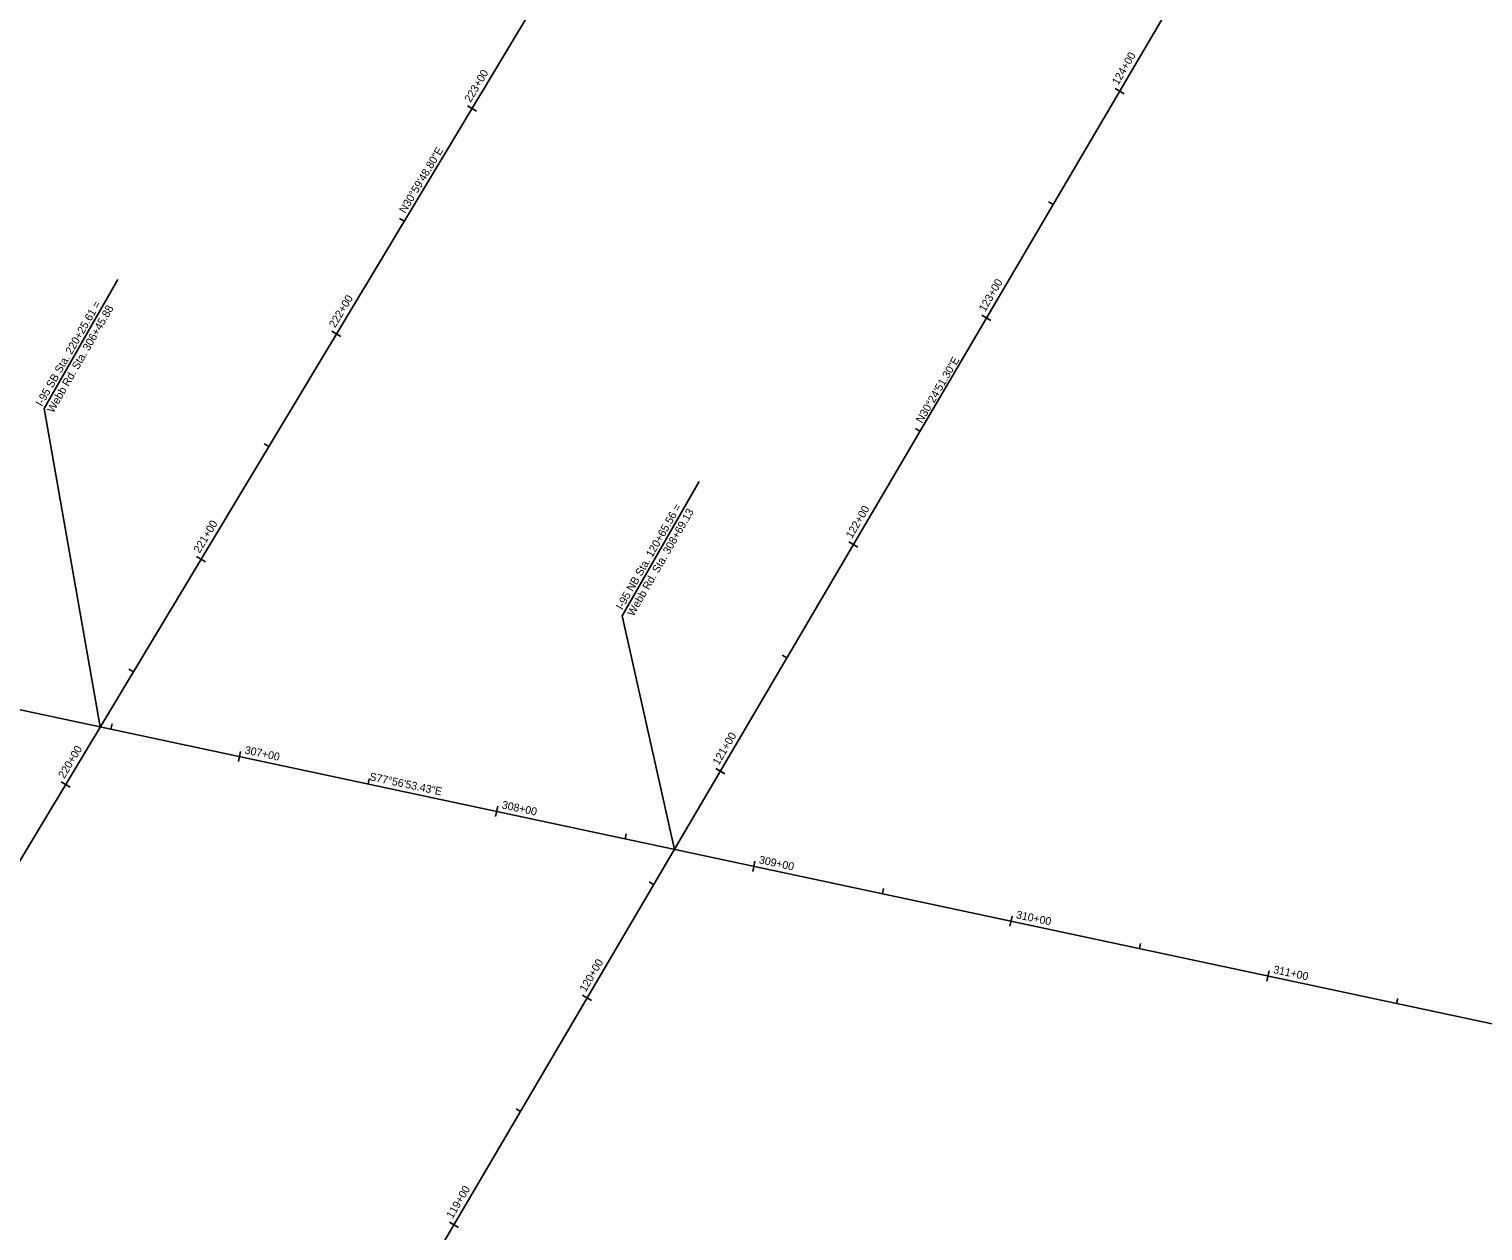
# Model space of a CAD drawing. Extents: x 1160279 to 1162288, y 615379 to 618896.
# Drawn here: x 1161178 to 1161731, y 617118 to 617576 of the extents above; entities that cross this region are included whole.
import ezdxf

# ---------------------------------------------------------------- set-up
doc = ezdxf.new("R2010")
doc.units = 0
for name, color, linetype in [('BRIDGE_TITLE', 7, 'Continuous'), ('FRAME', 7, 'Continuous'), ('HIGHWAY_TITLE', 7, 'Continuous'), ('MEDIUM', 7, 'Continuous')]:
    doc.layers.add(name, color=color, linetype=linetype)

msp = doc.modelspace()

# ---------------------------------------------------------------- linework, layer by layer
at = {"layer": 'FRAME'}
for p, q in [((1161056.19, 617062.15), (1162120.52, 618833.71)), ((1161209.81, 616899.51), (1162286.6, 618733.81)), ((1160573.57, 617445.06), (1162040.51, 617131.87))]:
    msp.add_line(p, q, dxfattribs=at)
at = {"layer": 'HIGHWAY_TITLE'}
for points in [[(1161591.12, 617553.02), (1161594.57, 617551)], [(1161344.81, 617546.45), (1161348.24, 617544.39)], [(1161565.81, 617509.9), (1161567.54, 617508.89)], [(1161319.06, 617503.59), (1161320.77, 617502.56)], [(1161540.5, 617466.78), (1161543.95, 617464.76)], [(1161293.31, 617460.73), (1161296.74, 617458.67)], [(1161515.19, 617423.66), (1161516.91, 617422.65)], [(1161267.56, 617417.87), (1161269.27, 617416.84)], [(1161489.87, 617380.54), (1161493.32, 617378.52)], [(1161241.81, 617375.01), (1161245.24, 617372.95)], [(1161464.56, 617337.42), (1161466.29, 617336.41)], [(1161216.06, 617332.15), (1161217.78, 617331.12)], [(1161209.66, 617311.3), (1161209.24, 617309.35)], [(1161258.56, 617300.86), (1161257.72, 617296.95)], [(1161190.31, 617289.29), (1161193.74, 617287.23)], [(1161307.46, 617290.42), (1161307.04, 617288.47)], [(1161439.25, 617294.3), (1161442.7, 617292.28)], [(1161356.35, 617279.98), (1161355.52, 617276.07)], [(1161405.25, 617269.54), (1161404.84, 617267.59)], [(1161454.15, 617259.1), (1161453.32, 617255.19)], [(1161413.94, 617251.19), (1161415.66, 617250.17)], [(1161503.05, 617248.66), (1161502.63, 617246.71)], [(1161551.95, 617238.22), (1161551.11, 617234.31)], [(1161600.84, 617227.78), (1161600.43, 617225.83)], [(1161649.74, 617217.34), (1161648.91, 617213.43)], [(1161388.62, 617208.07), (1161392.07, 617206.04)], [(1161698.64, 617206.9), (1161698.22, 617204.95)], [(1161363.31, 617164.95), (1161365.04, 617163.93)], [(1161338, 617121.83), (1161341.45, 617119.8)]]:
    msp.add_lwpolyline(points, dxfattribs=at)
at = {"layer": 'MEDIUM'}
for p, q in [((1161183.83, 617431.33), (1161211.93, 617480.31)), ((1161205.21, 617310.21), (1161183.83, 617431.33)), ((1161403.66, 617352.4), (1161432.96, 617403.48)), ((1161423.54, 617263.59), (1161403.66, 617352.4))]:
    msp.add_line(p, q, dxfattribs=at)

# ---------------------------------------------------------------- texts
at = {"layer": 'BRIDGE_TITLE'}
for s, rotation, p in [('N30%%d59\'48.80"E', 59.0031, (1161321.19, 617505.28)), ('N30%%d24\'51.30"E', 59.5857, (1161517.75, 617425.43)), ('S77%%d56\'53.43"E', 347.9482, (1161307.35, 617289.93))]:
    msp.add_text(s, height=3, rotation=rotation, dxfattribs=at).set_placement(p)
at = {"layer": 'HIGHWAY_TITLE'}
for s, rotation, p in [('124+00', 59.5857, (1161592.31, 617554.06)), ('223+00', 59.0031, (1161346.01, 617547.47)), ('123+00', 59.5857, (1161541.69, 617467.82)), ('222+00', 59.0031, (1161294.51, 617461.75)), ('122+00', 59.5857, (1161491.06, 617381.58)), ('221+00', 59.0031, (1161243.01, 617376.04)), ('121+00', 59.5857, (1161440.44, 617295.35)), ('220+00', 59.0031, (1161191.51, 617290.32)), ('307+00', 347.9482, (1161259.92, 617300.06)), ('308+00', 347.9482, (1161357.72, 617279.18)), ('309+00', 347.9482, (1161455.51, 617258.3)), ('310+00', 347.9482, (1161553.31, 617237.42)), ('120+00', 59.5857, (1161389.81, 617209.11)), ('311+00', 347.9482, (1161651.11, 617216.54)), ('119+00', 59.5857, (1161339.19, 617122.87))]:
    msp.add_text(s, height=3, rotation=rotation, dxfattribs=at).set_placement(p)
at = {"layer": 'MEDIUM'}
for s, p in [('I-95 SB Sta. 220+25.61 =', (1161183.01, 617431.84)), ('Webb Rd. Sta. 306+45.88', (1161187.35, 617429.35)), ('I-95 NB Sta. 120+65.56 =', (1161403.69, 617354.46)), ('Webb Rd. Sta. 308+69.13', (1161408.02, 617351.98))]:
    msp.add_text(s, height=3, rotation=60.1613, dxfattribs=at).set_placement(p)

doc.saveas('drawing.dxf')
